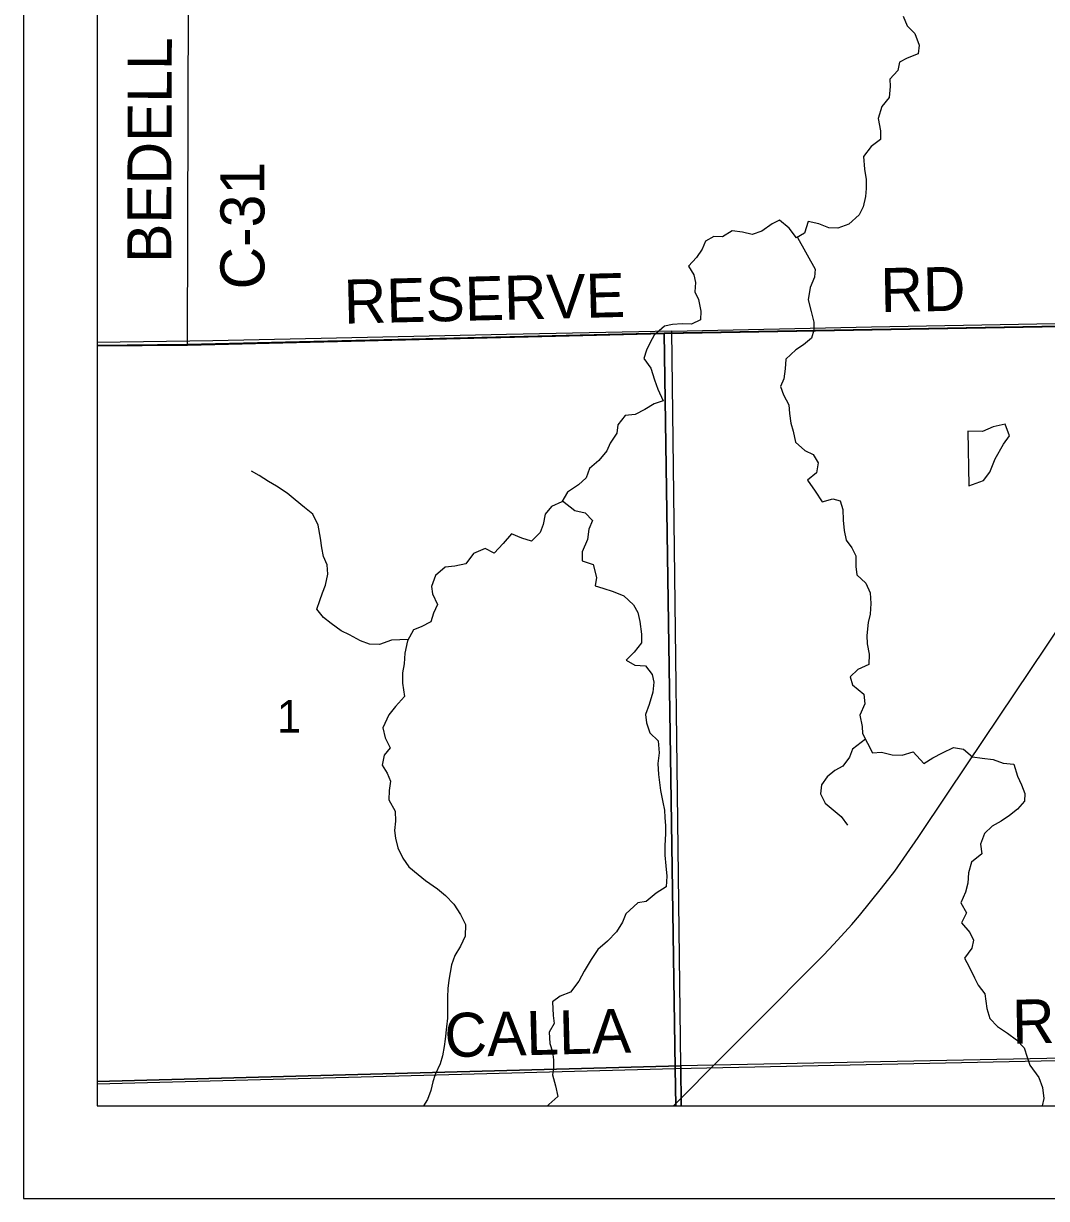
# Model space of a CAD drawing. Extents: x 0 to 34, y 0 to 22.
# Drawn here: x 2.895 to 4.215, y 13.887 to 15.405 of the extents above; entities that cross this region are included whole.
import ezdxf

# ---------------------------------------------------------------- set-up
doc = ezdxf.new("R2010")
doc.units = 0
for name, color, linetype in [('GM_X_Corporation', 7, 'Continuous'), ('GM_X_County_Road', 7, 'Continuous'), ('GM_X_County_Road_Text', 7, 'Continuous'), ('GM_X_Minor_Lake', 7, 'Continuous'), ('GM_X_Minor_River', 7, 'Continuous'), ('GM_X_Rail_Line', 7, 'Continuous'), ('GM_X_Section_Text', 7, 'Continuous'), ('GM_X_Township_Road', 7, 'Continuous'), ('GM_X_Township_Road_Text', 7, 'Continuous'), ('SH_Data', 7, 'Continuous')]:
    doc.layers.add(name, color=color, linetype=linetype)

msp = doc.modelspace()

# ---------------------------------------------------------------- linework, layer by layer
at = {"layer": 'GM_X_Corporation'}
msp.add_lwpolyline([(2.9895, 20.1176), (2.9895, 14.989), (3.1061, 14.9902), (3.7218, 15.0051), (5.1362, 15.0301), (5.7825, 15.0418), (6.0746, 15.0468), (7.3134, 15.0684), (7.3375, 15.0689), (7.3129, 15.9614), (7.3097, 16.0633), (7.3049, 16.5704), (7.3046, 16.5913), (7.2998, 16.7507), (7.2943, 16.935), (7.2911, 17.0516), (7.2872, 17.1772), (7.283, 17.3071)], dxfattribs=at)
for points in [[(3.7367, 14.0069), (9.7895, 14.0069), (9.7895, 15.1275), (8.8365, 15.1033), (8.3803, 15.0917), (7.3375, 15.0689), (7.3134, 15.0684), (6.0746, 15.0468), (5.7825, 15.0418), (5.1362, 15.0301), (3.7218, 15.0051), (3.7359, 14.0555)], [(4.7584, 15.0257), (4.774, 14.0793), (3.7432, 14.0588), (3.7317, 15.0075), (3.9896, 15.013), (4.4166, 15.021)], [(2.9895, 14.993), (2.9895, 14.0385), (3.7432, 14.0588), (3.7317, 15.0075), (3.5182, 15.0032), (3.1389, 14.9949)], [(2.9895, 14.989), (2.9895, 14.0069), (3.7367, 14.0069), (3.7359, 14.0555), (3.7218, 15.0051), (3.1061, 14.9902)], [(3.7439, 14.0069), (4.7752, 14.0069), (4.774, 14.0793), (3.7432, 14.0588)], [(2.9895, 14.0385), (2.9895, 14.0069), (3.7439, 14.0069), (3.7432, 14.0588)]]:
    msp.add_lwpolyline(points, close=True, dxfattribs=at)
at = {"layer": 'GM_X_County_Road'}
msp.add_line((3.1063, 14.9896), (3.1089, 15.8232), dxfattribs=at)
for points in [[(3.722, 15.0045), (5.1364, 15.0296), (5.7827, 15.0412), (6.0748, 15.0463), (7.3136, 15.0678)], [(2.9895, 14.9885), (3.1063, 14.9896), (3.722, 15.0045)]]:
    msp.add_lwpolyline(points, dxfattribs=at)
at = {"layer": 'GM_X_Minor_Lake'}
for points in [[(4.1151, 14.8078), (4.1339, 14.8146), (4.1421, 14.8254), (4.149, 14.8426), (4.16, 14.8615), (4.1677, 14.8722), (4.1621, 14.8873), (4.1467, 14.884), (4.1328, 14.878), (4.1138, 14.8784)], [(4.1138, 14.8784), (4.1151, 14.8078)]]:
    msp.add_lwpolyline(points, dxfattribs=at)
at = {"layer": 'GM_X_Minor_River'}
for points in [[(4.0304, 15.4143), (4.0355, 15.4019), (4.0456, 15.3922), (4.0511, 15.3771), (4.0498, 15.3657), (4.0356, 15.3601), (4.0258, 15.355), (4.0237, 15.3443), (4.0133, 15.3331), (4.0135, 15.3236), (4.0122, 15.3092), (4.003, 15.2976), (3.9983, 15.2823), (4.0013, 15.2664), (4.0011, 15.255), (3.9892, 15.2461), (3.9792, 15.2333), (3.9806, 15.217), (3.9828, 15.2034), (3.9826, 15.192), (3.9816, 15.1817), (3.9789, 15.168), (3.9737, 15.158), (3.9603, 15.1456), (3.946, 15.1404), (3.9343, 15.1409), (3.9213, 15.1464), (3.9076, 15.1492), (3.903, 15.1343), (3.8928, 15.128), (3.8831, 15.1407), (3.8708, 15.1508), (3.8611, 15.146), (3.848, 15.1367), (3.8352, 15.1326), (3.823, 15.1354), (3.8097, 15.1371), (3.7973, 15.1296), (3.786, 15.1298), (3.7751, 15.1239), (3.7707, 15.1135), (3.7637, 15.1028), (3.753, 15.0916), (3.76, 15.0803), (3.7621, 15.0705), (3.7615, 15.0583), (3.7659, 15.0485), (3.7692, 15.0334), (3.7686, 15.0223), (3.757, 15.0168), (3.7449, 15.0169), (3.7324, 15.016), (3.7222, 15.0142), (3.7088, 15.0026), (3.7036, 14.993), (3.6989, 14.983), (3.6957, 14.9723), (3.7046, 14.9596), (3.7095, 14.9445), (3.7135, 14.9328), (3.7206, 14.9177), (3.7089, 14.9137), (3.6969, 14.9063), (3.6845, 14.9), (3.6713, 14.8986), (3.662, 14.8866), (3.6607, 14.8756), (3.6522, 14.8629), (3.6479, 14.8529), (3.6375, 14.8406), (3.6252, 14.8301), (3.6212, 14.8182), (3.6112, 14.8089)], [(3.8938, 15.1286), (3.9167, 15.0878), (3.9158, 15.0775), (3.9103, 15.0641), (3.9076, 15.0481), (3.9117, 15.033), (3.9149, 15.019), (3.9151, 15.0088), (3.9119, 14.9985), (3.9015, 14.9899), (3.8917, 14.9836), (3.8787, 14.9716), (3.8782, 14.9591), (3.8765, 14.9461), (3.8718, 14.9362), (3.8758, 14.9252), (3.8828, 14.9124), (3.8838, 14.9014), (3.8852, 14.8886), (3.8884, 14.8784), (3.8913, 14.864), (3.9036, 14.8536), (3.9143, 14.8481), (3.9206, 14.8376), (3.9185, 14.8246), (3.907, 14.8153), (3.9167, 14.801), (3.9257, 14.7871), (3.9396, 14.7908), (3.9491, 14.7883), (3.9524, 14.7774), (3.953, 14.7633), (3.954, 14.7501), (3.9569, 14.7376), (3.9643, 14.7275), (3.9694, 14.7173), (3.9693, 14.7036), (3.9706, 14.693), (3.9822, 14.6822), (3.9877, 14.6698), (3.9887, 14.6558), (3.9879, 14.6421), (3.9854, 14.6314), (3.9834, 14.6146), (3.984, 14.6036), (3.9865, 14.5904), (3.986, 14.5771), (3.9717, 14.5707), (3.9621, 14.5611), (3.9649, 14.5509), (3.9795, 14.5386), (3.9809, 14.5261), (3.9744, 14.5115), (3.9773, 14.4971), (3.9778, 14.4877), (3.9845, 14.4753), (3.9908, 14.4628), (4.0025, 14.4638), (4.0162, 14.4603), (4.0291, 14.4598), (4.0431, 14.4642), (4.057, 14.4493), (4.0686, 14.4563), (4.081, 14.463), (4.0952, 14.4697), (4.1085, 14.4677), (4.1201, 14.4577), (4.1326, 14.456), (4.1467, 14.4544), (4.1596, 14.4497), (4.1733, 14.4484), (4.1781, 14.433), (4.1833, 14.4217), (4.1873, 14.4103), (4.1871, 14.4005), (4.1778, 14.39), (4.1677, 14.3822), (4.1569, 14.3748), (4.1452, 14.3681), (4.1352, 14.3588), (4.1301, 14.3451), (4.1319, 14.3326), (4.1188, 14.3217), (4.1149, 14.3079), (4.114, 14.2946), (4.1108, 14.2828), (4.105, 14.2694), (4.1121, 14.2562), (4.1059, 14.2432), (4.1163, 14.2308), (4.1214, 14.2211), (4.119, 14.2108), (4.1094, 14.1977), (4.1156, 14.1864), (4.1223, 14.1725), (4.1271, 14.1627), (4.136, 14.1518), (4.1382, 14.1329), (4.1423, 14.1197), (4.1523, 14.1096), (4.165, 14.1007)], [(3.3912, 14.6092), (3.3698, 14.6084), (3.354, 14.6028), (3.3414, 14.6033), (3.3296, 14.6076), (3.3155, 14.6153), (3.3048, 14.6204), (3.2917, 14.6301), (3.2821, 14.6379), (3.2735, 14.6487), (3.2771, 14.6598), (3.2807, 14.6697), (3.2847, 14.6797), (3.2875, 14.6938), (3.2865, 14.7056), (3.2821, 14.7165), (3.2797, 14.7278), (3.2779, 14.74), (3.2749, 14.757), (3.2682, 14.7713), (3.2575, 14.7798), (3.2452, 14.7895), (3.2348, 14.7984), (3.2213, 14.8073), (3.211, 14.8135), (3.1987, 14.8213), (3.1888, 14.8268)], [(3.6112, 14.8089), (3.597, 14.7995), (3.5896, 14.7873), (3.5761, 14.7813), (3.5683, 14.7713), (3.5655, 14.7579), (3.5616, 14.7476), (3.5504, 14.7364), (3.5382, 14.7403), (3.5248, 14.7458), (3.5141, 14.7334), (3.5022, 14.721), (3.4907, 14.7269), (3.4757, 14.7205), (3.4657, 14.707), (3.4517, 14.7041), (3.4392, 14.7027), (3.4266, 14.6919), (3.4215, 14.6777), (3.4225, 14.6682), (3.4291, 14.6547), (3.4241, 14.6432), (3.4205, 14.6321), (3.4081, 14.6258), (3.3983, 14.6218), (3.3902, 14.6076), (3.3871, 14.5916), (3.3859, 14.5779), (3.3838, 14.5661), (3.3841, 14.5528), (3.3866, 14.5358), (3.3748, 14.5226), (3.3662, 14.5118), (3.3586, 14.4953), (3.3615, 14.4821), (3.3678, 14.4693), (3.3604, 14.4597), (3.3576, 14.4471), (3.3642, 14.4366), (3.3686, 14.4264), (3.3669, 14.4142), (3.3664, 14.4021), (3.3746, 14.3874), (3.3749, 14.3745), (3.3736, 14.3627), (3.3749, 14.3528), (3.3781, 14.3404), (3.3845, 14.3268), (3.3922, 14.3156), (3.4042, 14.3059), (3.4138, 14.2981), (3.4291, 14.2874), (3.4395, 14.2785), (3.4503, 14.2673), (3.4589, 14.2541), (3.4652, 14.241), (3.4647, 14.2261), (3.4589, 14.2131), (3.4516, 14.2012), (3.4472, 14.1893), (3.4455, 14.1791), (3.4438, 14.1692), (3.4425, 14.1585), (3.442, 14.1475), (3.4422, 14.1353), (3.4421, 14.1201), (3.4408, 14.1091), (3.4388, 14.0931), (3.4375, 14.0836), (3.4354, 14.0714), (3.4326, 14.0611), (3.426, 14.0476), (3.4231, 14.0381), (3.4203, 14.0266), (3.4164, 14.0152), (3.4111, 14.0069)], [(3.5903, 14.7884), (3.6065, 14.7758), (3.6198, 14.773), (3.6291, 14.7629), (3.6244, 14.7518), (3.6227, 14.7385), (3.6158, 14.7224), (3.6157, 14.711), (3.6301, 14.706), (3.6346, 14.6893), (3.6325, 14.6787), (3.6428, 14.6754), (3.6558, 14.6715), (3.6695, 14.6657), (3.6823, 14.6542), (3.6877, 14.644), (3.6902, 14.6327), (3.6924, 14.6164), (3.6923, 14.605), (3.683, 14.593), (3.6726, 14.5826), (3.6837, 14.5763), (3.6977, 14.5751), (3.7063, 14.5642), (3.7083, 14.5544), (3.7071, 14.5411), (3.7024, 14.5254), (3.6978, 14.5124), (3.6991, 14.5018), (3.7031, 14.4889), (3.7139, 14.4785), (3.7153, 14.463), (3.7137, 14.4493), (3.7144, 14.4348), (3.717, 14.4144), (3.7199, 14.3992), (3.722, 14.389), (3.7226, 14.3795), (3.7235, 14.3685), (3.7233, 14.3583), (3.7225, 14.3434), (3.7227, 14.3309), (3.7241, 14.3169), (3.7251, 14.3036), (3.7242, 14.2899), (3.7115, 14.2817), (3.6984, 14.2708), (3.6879, 14.2691), (3.6722, 14.2551), (3.6679, 14.2444), (3.6601, 14.2317), (3.6486, 14.2197), (3.6363, 14.2089), (3.6275, 14.1962), (3.6183, 14.1808), (3.6117, 14.1678), (3.601, 14.1539), (3.5874, 14.1487), (3.5777, 14.1413), (3.5784, 14.1238), (3.5797, 14.1132), (3.5735, 14.1021), (3.5742, 14.0873), (3.5778, 14.0767), (3.5791, 14.0665), (3.5789, 14.0566), (3.5776, 14.0471), (3.5816, 14.0327), (3.5845, 14.0191), (3.573, 14.0086), (3.5711, 14.0069)], [(3.9817, 14.4805), (3.9649, 14.4677), (3.961, 14.4573), (3.9525, 14.4458), (3.942, 14.4399), (3.9323, 14.4321), (3.9249, 14.4217), (3.9236, 14.4099), (3.9295, 14.3979), (3.9402, 14.3893), (3.9503, 14.3808), (3.9584, 14.3695)], [(4.165, 14.1007), (4.1769, 14.0922), (4.1865, 14.0821), (4.1906, 14.0697), (4.1938, 14.0595), (4.2054, 14.0434), (4.2102, 14.0305), (4.212, 14.0165), (4.2098, 14.0069)]]:
    msp.add_lwpolyline(points, dxfattribs=at)
at = {"layer": 'GM_X_Rail_Line'}
msp.add_lwpolyline([(3.7337, 14.0069), (3.7442, 14.0174), (3.7874, 14.0609), (3.8187, 14.0922), (3.8553, 14.1289), (3.9075, 14.1814), (3.9279, 14.202), (3.9404, 14.2154), (3.9504, 14.2263), (3.9641, 14.2413), (3.9738, 14.2529), (3.9884, 14.2703), (4.0022, 14.288), (4.0195, 14.3102), (4.0352, 14.3324), (4.0497, 14.3535), (4.0882, 14.4109), (4.1345, 14.4801), (4.2148, 14.5996), (4.263, 14.6716)], dxfattribs=at)
at = {"layer": 'GM_X_Township_Road'}
for p, q in [((3.733, 14.2627), (3.722, 15.0045)), ((3.7361, 14.055), (3.733, 14.2627)), ((3.7361, 14.055), (4.8042, 14.0781)), ((2.9895, 14.0355), (3.7361, 14.055)), ((3.7369, 14.0069), (3.7361, 14.055))]:
    msp.add_line(p, q, dxfattribs=at)
at = {"layer": 'SH_Data'}
for p, q in [((2.8945, 20.8873), (2.8945, 13.8873)), ((2.8945, 13.8873), (9.8945, 13.8873))]:
    msp.add_line(p, q, dxfattribs=at)

# ---------------------------------------------------------------- texts
at = {"layer": 'GM_X_County_Road_Text'}
for s, rotation, p in [('BEDELL', 89.8205, (3.0852, 15.0957)), ('C-31', 90, (3.2056, 15.0615)), ('RD', 0.9872, (4.0015, 15.0322)), ('RESERVE', 1.3932, (3.3088, 15.0172))]:
    msp.add_text(s, height=0.05682, rotation=rotation, dxfattribs=at).set_placement(p)
at = {"layer": 'GM_X_Section_Text'}
msp.add_text('1', height=0.0419, rotation=0, dxfattribs=at).set_placement((3.2218, 14.4891))
at = {"layer": 'GM_X_Township_Road_Text'}
for s, rotation, p in [('RD', 0.9891, (4.1715, 14.0872)), ('CALLA', 1.4424, (3.4388, 14.0697))]:
    msp.add_text(s, height=0.05682, rotation=rotation, dxfattribs=at).set_placement(p)

doc.saveas('drawing.dxf')
